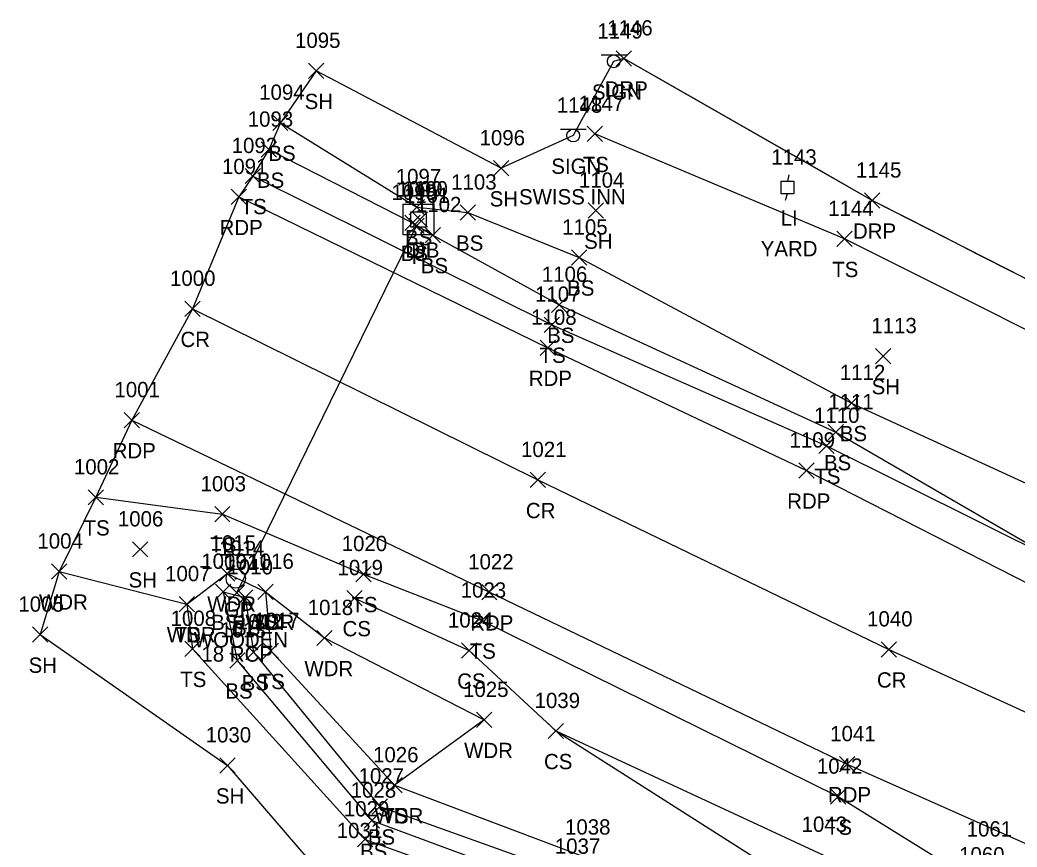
# Model space of a CAD drawing. Extents: x 1547013 to 1549434, y 267998 to 268739.
# Drawn here: x 1548262.7 to 1548393.1, y 268166.7 to 268275 of the extents above; entities that cross this region are included whole.
import ezdxf

# ---------------------------------------------------------------- set-up
doc = ezdxf.new("R2010")
doc.units = 0
for name, color, linetype in [('D_A', 7, 'Continuous'), ('D_C', 7, 'Continuous'), ('D_I', 7, 'Continuous'), ('D_TIC', 7, 'Continuous'), ('DCP', 7, 'Continuous'), ('DS', 7, 'Continuous'), ('L_A', 7, 'Continuous'), ('L_I', 7, 'Continuous'), ('L_TIC', 7, 'Continuous'), ('LAWA', 7, 'Continuous'), ('LELB', 7, 'Continuous'), ('LSOGP', 7, 'Continuous'), ('P_A', 7, 'Continuous'), ('P_I', 7, 'Continuous'), ('P_TIC', 7, 'Continuous'), ('PET', 7, 'Continuous'), ('PRC', 7, 'Continuous'), ('R_A', 7, 'Continuous'), ('R_C', 7, 'Continuous'), ('R_I', 7, 'Continuous'), ('R_TIC', 7, 'Continuous'), ('RDP', 7, 'Continuous'), ('RGP', 7, 'Continuous'), ('S_A', 7, 'Continuous'), ('S_C', 7, 'Continuous'), ('S_I', 7, 'Continuous'), ('SSGN', 7, 'Continuous'), ('U_A', 7, 'Continuous'), ('U_C', 7, 'Continuous'), ('U_I', 7, 'Continuous'), ('ULP', 7, 'Continuous')]:
    doc.layers.add(name, color=color, linetype=linetype)

msp = doc.modelspace()

# ---------------------------------------------------------------- linework, layer by layer
at = {"layer": 'D_TIC'}
for points in [[(1548313.99, 268247.85), (1548315.99, 268249.85)], [(1548315.99, 268247.85), (1548313.99, 268249.85)], [(1548313.54, 268247.01), (1548315.54, 268249.01)], [(1548315.54, 268247.01), (1548313.54, 268249.01)], [(1548290.04, 268198.97), (1548292.04, 268200.97)], [(1548292.04, 268198.97), (1548290.04, 268200.97)]]:
    msp.add_lwpolyline(points, dxfattribs=at)
at = {"layer": 'DCP'}
msp.add_lwpolyline([(1548291.04, 268199.97), (1548314.54, 268248.01)], dxfattribs=at)
at = {"layer": 'DS'}
for p, q in [((1548312.8, 268250.84), (1548316.8, 268250.84)), ((1548312.8, 268246.84), (1548312.8, 268250.84)), ((1548313.8, 268247.84), (1548313.8, 268249.84)), ((1548313.8, 268249.84), (1548315.8, 268249.84)), ((1548315.8, 268249.84), (1548315.8, 268247.84)), ((1548316.8, 268250.84), (1548316.8, 268246.84)), ((1548314.8, 268248.84), (1548314.8, 268248.84)), ((1548314.8, 268248.84), (1548314.8, 268248.84)), ((1548315.8, 268247.84), (1548313.8, 268247.84)), ((1548316.8, 268246.84), (1548312.8, 268246.84))]:
    msp.add_line(p, q, dxfattribs=at)
at = {"layer": 'L_TIC'}
for points in [[(1548300.42, 268267.29), (1548302.42, 268269.29)], [(1548302.42, 268267.29), (1548300.42, 268269.29)], [(1548295.73, 268260.5), (1548297.73, 268262.5)], [(1548297.73, 268260.5), (1548295.73, 268262.5)], [(1548336.89, 268259.04), (1548338.89, 268261.04)], [(1548338.89, 268259.04), (1548336.89, 268261.04)], [(1548294.23, 268256.98), (1548296.23, 268258.98)], [(1548296.23, 268256.98), (1548294.23, 268258.98)], [(1548324.63, 268254.54), (1548326.63, 268256.54)], [(1548326.63, 268254.54), (1548324.63, 268256.54)], [(1548292.13, 268253.53), (1548294.13, 268255.53)], [(1548294.13, 268253.53), (1548292.13, 268255.53)], [(1548313.6, 268249.46), (1548315.6, 268251.46)], [(1548315.6, 268249.46), (1548313.6, 268251.46)], [(1548337, 268249), (1548339, 268251)], [(1548339, 268249), (1548337, 268251)], [(1548320.28, 268248.75), (1548322.28, 268250.75)], [(1548322.28, 268248.75), (1548320.28, 268250.75)], [(1548313.04, 268247.41), (1548315.04, 268249.41)], [(1548315.04, 268247.41), (1548313.04, 268249.41)], [(1548315.67, 268245.8), (1548317.67, 268247.8)], [(1548317.67, 268245.8), (1548315.67, 268247.8)], [(1548369.54, 268245.3), (1548371.54, 268247.3)], [(1548371.54, 268245.3), (1548369.54, 268247.3)], [(1548334.82, 268242.87), (1548336.82, 268244.87)], [(1548336.82, 268242.87), (1548334.82, 268244.87)], [(1548332.21, 268236.68), (1548334.21, 268238.68)], [(1548334.21, 268236.68), (1548332.21, 268238.68)], [(1548331.25, 268234.07), (1548333.25, 268236.07)], [(1548333.25, 268234.07), (1548331.25, 268236.07)], [(1548374.62, 268229.96), (1548376.62, 268231.96)], [(1548376.62, 268229.96), (1548374.62, 268231.96)], [(1548370.49, 268223.82), (1548372.49, 268225.82)], [(1548372.49, 268223.82), (1548370.49, 268225.82)], [(1548368.42, 268220.01), (1548370.42, 268222.01)], [(1548370.42, 268220.01), (1548368.42, 268222.01)], [(1548367.2, 268218.22), (1548369.2, 268220.22)], [(1548369.2, 268218.22), (1548367.2, 268220.22)], [(1548271.57, 268211.48), (1548273.57, 268213.48)], [(1548273.57, 268211.48), (1548271.57, 268213.48)], [(1548288.14, 268209.26), (1548290.14, 268211.26)], [(1548290.14, 268209.26), (1548288.14, 268211.26)], [(1548277.38, 268204.67), (1548279.38, 268206.67)], [(1548279.38, 268204.67), (1548277.38, 268206.67)], [(1548266.79, 268201.77), (1548268.79, 268203.77)], [(1548268.79, 268201.77), (1548266.79, 268203.77)], [(1548288.79, 268201.51), (1548290.79, 268203.51)], [(1548290.79, 268201.51), (1548288.79, 268203.51)], [(1548306.62, 268201.44), (1548308.62, 268203.44)], [(1548308.62, 268201.44), (1548306.62, 268203.44)], [(1548288.24, 268199.12), (1548290.24, 268201.12)], [(1548290.24, 268199.12), (1548288.24, 268201.12)], [(1548288.24, 268199.12), (1548290.24, 268201.12)], [(1548290.24, 268199.12), (1548288.24, 268201.12)], [(1548291.11, 268198.39), (1548293.11, 268200.39)], [(1548293.11, 268198.39), (1548291.11, 268200.39)], [(1548293.8, 268199.12), (1548295.8, 268201.12)], [(1548295.8, 268199.12), (1548293.8, 268201.12)], [(1548293.8, 268199.12), (1548295.8, 268201.12)], [(1548295.8, 268199.12), (1548293.8, 268201.12)], [(1548305.43, 268198.29), (1548307.43, 268200.29)], [(1548307.43, 268198.29), (1548305.43, 268200.29)], [(1548283.5, 268197.5), (1548285.5, 268199.5)], [(1548285.5, 268197.5), (1548283.5, 268199.5)], [(1548283.5, 268197.5), (1548285.5, 268199.5)], [(1548285.5, 268197.5), (1548283.5, 268199.5)], [(1548322.1, 268195.35), (1548324.1, 268197.35)], [(1548324.1, 268195.35), (1548322.1, 268197.35)], [(1548264.3, 268193.51), (1548266.3, 268195.51)], [(1548266.3, 268193.51), (1548264.3, 268195.51)], [(1548301.52, 268193.07), (1548303.52, 268195.07)], [(1548303.52, 268193.07), (1548301.52, 268195.07)], [(1548284.22, 268191.65), (1548286.22, 268193.65)], [(1548286.22, 268191.65), (1548284.22, 268193.65)], [(1548292.23, 268191.21), (1548294.23, 268193.21)], [(1548294.23, 268191.21), (1548292.23, 268193.21)], [(1548294.49, 268191.38), (1548296.49, 268193.38)], [(1548296.49, 268191.38), (1548294.49, 268193.38)], [(1548320.43, 268191.43), (1548322.43, 268193.43)], [(1548322.43, 268191.43), (1548320.43, 268193.43)], [(1548290.1, 268190.14), (1548292.1, 268192.14)], [(1548292.1, 268190.14), (1548290.1, 268192.14)], [(1548322.41, 268182.35), (1548324.41, 268184.35)], [(1548324.41, 268182.35), (1548322.41, 268184.35)], [(1548331.78, 268180.9), (1548333.78, 268182.9)], [(1548333.78, 268180.9), (1548331.78, 268182.9)], [(1548331.78, 268180.9), (1548333.78, 268182.9)], [(1548333.78, 268180.9), (1548331.78, 268182.9)], [(1548288.82, 268176.4), (1548290.82, 268178.4)], [(1548290.82, 268176.4), (1548288.82, 268178.4)], [(1548310.68, 268173.8), (1548312.68, 268175.8)], [(1548312.68, 268173.8), (1548310.68, 268175.8)], [(1548310.68, 268173.8), (1548312.68, 268175.8)], [(1548312.68, 268173.8), (1548310.68, 268175.8)], [(1548368.71, 268172.31), (1548370.71, 268174.31)], [(1548370.71, 268172.31), (1548368.71, 268174.31)], [(1548308.74, 268171.03), (1548310.74, 268173.03)], [(1548310.74, 268171.03), (1548308.74, 268173.03)], [(1548307.71, 268169.17), (1548309.71, 268171.17)], [(1548309.71, 268169.17), (1548307.71, 268171.17)], [(1548306.82, 268166.72), (1548308.82, 268168.72)], [(1548308.82, 268166.72), (1548306.82, 268168.72)]]:
    msp.add_lwpolyline(points, dxfattribs=at)
at = {"layer": 'LAWA'}
msp.add_lwpolyline([(1548267.79, 268202.77), (1548284.5, 268198.5), (1548289.79, 268202.51), (1548294.8, 268200.12), (1548302.52, 268194.07), (1548323.41, 268183.35), (1548311.68, 268174.8)], dxfattribs=at)
at = {"layer": 'LELB'}
for points in [[(1548296.73, 268261.5), (1548314.6, 268250.46), (1548321.28, 268249.75), (1548335.82, 268243.87), (1548371.49, 268224.82), (1548401.22, 268211.16), (1548434.01, 268190.91)], [(1548293.13, 268254.53), (1548332.25, 268235.07), (1548368.2, 268219.22), (1548398.43, 268204.17), (1548432.39, 268188.56), (1548470.91, 268170.21), (1548496.62, 268162.55), (1548482.16, 268178.12), (1548462.07, 268192.9), (1548441.51, 268207.34), (1548411.84, 268225.63), (1548370.54, 268246.3), (1548337.89, 268260.04)], [(1548295.23, 268257.98), (1548314.04, 268248.41), (1548316.67, 268246.8), (1548333.21, 268237.68), (1548369.42, 268221.01), (1548398.43, 268204.17)], [(1548272.57, 268212.48), (1548289.14, 268210.26), (1548307.62, 268202.44), (1548323.1, 268196.35), (1548369.71, 268173.31), (1548388.46, 268161.7), (1548422.32, 268150.28), (1548459.33, 268134.33), (1548490.6, 268122.37), (1548528.34, 268109.13), (1548567.41, 268095.24), (1548592.2, 268086.56), (1548606.66, 268079.82), (1548620.32, 268072.15), (1548638.75, 268065.65), (1548644.4, 268061.61), (1548647.64, 268052.81), (1548649.6, 268041.05)], [(1548289.24, 268200.12), (1548292.11, 268199.39), (1548293.23, 268192.21), (1548309.74, 268172.03), (1548335.42, 268162.83), (1548365.1, 268153.15), (1548400.46, 268134.44), (1548414.42, 268125.58), (1548450.52, 268108.18), (1548480.18, 268096.43), (1548525.56, 268079.65), (1548533.49, 268078.22), (1548538.36, 268080.07), (1548548.83, 268079.87)], [(1548289.24, 268200.12), (1548291.1, 268191.14), (1548308.71, 268170.17), (1548334.15, 268160.77), (1548364.93, 268151.69), (1548400.57, 268132.64), (1548414.23, 268124.12), (1548450.61, 268106.02), (1548479.71, 268095.13), (1548525.1, 268077.98), (1548532.42, 268076.13)], [(1548294.8, 268200.12), (1548295.49, 268192.38), (1548311.68, 268174.8), (1548336.75, 268165.34), (1548365.8, 268156.23), (1548401.93, 268136.68), (1548414.05, 268129.03)], [(1548306.43, 268199.29), (1548321.43, 268192.43), (1548332.78, 268181.9), (1548367.71, 268165.7), (1548391.94, 268148.16), (1548415.52, 268137.54), (1548452.83, 268119.09), (1548479.13, 268107.94), (1548530.85, 268089.69)], [(1548284.5, 268198.5), (1548285.22, 268192.65), (1548307.82, 268167.72), (1548333.45, 268158.51), (1548364.16, 268149.82), (1548400.06, 268131.43), (1548413.58, 268123.14), (1548450.66, 268104.52)], [(1548332.78, 268181.9), (1548366.56, 268160.4), (1548391.94, 268148.16)]]:
    msp.add_lwpolyline(points, dxfattribs=at)
at = {"layer": 'LSOGP'}
msp.add_lwpolyline([(1548397.39, 268239.51), (1548392.75, 268241.87), (1548388.1, 268244.23), (1548383.46, 268246.6), (1548378.82, 268248.96), (1548374.18, 268251.32), (1548366.05, 268255.97), (1548357.93, 268260.62), (1548349.8, 268265.27), (1548341.68, 268269.92), (1548340.34, 268269.52), (1548335.03, 268259.81), (1548325.63, 268255.54), (1548301.42, 268268.29), (1548296.73, 268261.5), (1548295.23, 268257.98), (1548293.13, 268254.53), (1548291.29, 268251.79), (1548285.23, 268237.15), (1548277.31, 268222.58), (1548272.57, 268212.48), (1548267.79, 268202.77), (1548265.3, 268194.51), (1548289.82, 268177.4), (1548304.9, 268159.85)], dxfattribs=at)
at = {"layer": 'P_TIC'}
for points in [[(1548290.29, 268250.79), (1548292.29, 268252.79)], [(1548292.29, 268250.79), (1548290.29, 268252.79)], [(1548284.23, 268236.15), (1548286.23, 268238.15)], [(1548286.23, 268236.15), (1548284.23, 268238.15)], [(1548330.75, 268231.06), (1548332.75, 268233.06)], [(1548332.75, 268231.06), (1548330.75, 268233.06)], [(1548276.31, 268221.58), (1548278.31, 268223.58)], [(1548278.31, 268221.58), (1548276.31, 268223.58)], [(1548329.43, 268213.75), (1548331.43, 268215.75)], [(1548331.43, 268213.75), (1548329.43, 268215.75)], [(1548364.57, 268214.99), (1548366.57, 268216.99)], [(1548366.57, 268214.99), (1548364.57, 268216.99)], [(1548323.08, 268199.05), (1548325.08, 268201.05)], [(1548325.08, 268199.05), (1548323.08, 268201.05)], [(1548375.37, 268191.58), (1548377.37, 268193.58)], [(1548377.37, 268191.58), (1548375.37, 268193.58)], [(1548369.89, 268176.56), (1548371.89, 268178.56)], [(1548371.89, 268176.56), (1548369.89, 268178.56)]]:
    msp.add_lwpolyline(points, dxfattribs=at)
at = {"layer": 'PET'}
for points in [[(1548291.29, 268251.79), (1548331.75, 268232.06), (1548365.57, 268215.99), (1548397.04, 268199.92), (1548430.53, 268185.01), (1548469.56, 268167.88), (1548505.57, 268153.53), (1548548.45, 268139.73), (1548572.84, 268130.65), (1548596.65, 268123.57), (1548616.57, 268118.19), (1548655.34, 268109.04), (1548680.93, 268103.12), (1548700.8, 268099.76), (1548753.55, 268092.31), (1548788.11, 268088.53), (1548842.08, 268084.26), (1548868.98, 268083.24)], [(1548277.31, 268222.58), (1548324.08, 268200.05), (1548370.89, 268177.56), (1548421.34, 268155.12), (1548457.66, 268139.55), (1548491.25, 268126.1), (1548528.96, 268112.02), (1548568.2, 268099.41), (1548604.28, 268089.49), (1548621.9, 268083.87), (1548638.12, 268079.83), (1548660.94, 268075.04), (1548683.04, 268070.81), (1548718.59, 268065.27), (1548750.02, 268060.75), (1548786.09, 268057.26), (1548818, 268054.36), (1548866.14, 268051.84)]]:
    msp.add_lwpolyline(points, dxfattribs=at)
at = {"layer": 'PRC'}
msp.add_lwpolyline([(1548285.23, 268237.15), (1548330.43, 268214.75), (1548376.37, 268192.58), (1548426.54, 268169.59), (1548464.29, 268153.5), (1548497.35, 268140.09), (1548534.69, 268126.49), (1548572.93, 268114.69), (1548608.02, 268104.77), (1548637.81, 268097.38), (1548663.07, 268091.69), (1548686.38, 268086.96), (1548723.69, 268081.05), (1548751.9, 268076.9), (1548786.74, 268073.36), (1548818.76, 268070.54), (1548866.8, 268068.08)], dxfattribs=at)
at = {"layer": 'R_TIC'}
for points in [[(1548340.68, 268268.92), (1548342.68, 268270.92)], [(1548342.68, 268268.92), (1548340.68, 268270.92)], [(1548373.18, 268250.32), (1548375.18, 268252.32)], [(1548375.18, 268250.32), (1548373.18, 268252.32)]]:
    msp.add_lwpolyline(points, dxfattribs=at)
at = {"layer": 'RDP'}
msp.add_lwpolyline([(1548505.57, 268153.53), (1548507.08, 268156.6), (1548497.9, 268167.16), (1548485.25, 268181.3), (1548463.54, 268201.58), (1548445.25, 268213.44), (1548411.31, 268232.42), (1548374.18, 268251.32), (1548341.68, 268269.92)], dxfattribs=at)
at = {"layer": 'RGP'}
msp.add_line((1548290.9, 268201.84), (1548290.9, 268201.84), dxfattribs=at)
for radius in [1.25, 0.0833]:
    msp.add_circle((1548290.9, 268201.84), radius, dxfattribs=at)
at = {"layer": 'SSGN'}
for p, q in [((1548338.71, 268270.37), (1548342.05, 268270.37)), ((1548340.36, 268269.54), (1548340.36, 268269.54)), ((1548333.41, 268260.67), (1548336.74, 268260.67)), ((1548335.05, 268259.83), (1548335.05, 268259.83))]:
    msp.add_line(p, q, dxfattribs=at)
for centre in [(1548340.36, 268269.54), (1548335.05, 268259.83)]:
    msp.add_circle(centre, 0.833, dxfattribs=at)
at = {"layer": 'ULP'}
for p, q in [((1548362.26, 268252.19), (1548362.26, 268253.85)), ((1548362.26, 268253.85), (1548363.93, 268253.85)), ((1548363.26, 268254.69), (1548363.09, 268253.85)), ((1548363.93, 268253.85), (1548363.93, 268252.19)), ((1548363.09, 268253.02), (1548363.09, 268253.02)), ((1548363.93, 268252.19), (1548362.26, 268252.19)), ((1548362.84, 268251.35), (1548363.09, 268252.19))]:
    msp.add_line(p, q, dxfattribs=at)

# ---------------------------------------------------------------- texts
at = {"layer": 'D_A'}
for s, p in [('DIB', (1548313.09, 268243.85)), ('DI', (1548313.86, 268243.84)), ('P', (1548313.91, 268243.01)), ('P', (1548290.42, 268194.97))]:
    msp.add_text(s, height=2, dxfattribs=at).set_placement(p)
at = {"layer": 'D_C'}
msp.add_text('18 RCP', height=2, dxfattribs=at).set_placement((1548286.4, 268190.97))
at = {"layer": 'D_I'}
for s, p in [('1099', (1548312.02, 268251.84)), ('1100', (1548312.7, 268251.85)), ('1101', (1548312.9, 268251.01)), ('1011', (1548289.4, 268202.97))]:
    msp.add_text(s, height=2, dxfattribs=at).set_placement(p)
at = {"layer": 'L_A'}
for s, p in [('SH', (1548299.91, 268263.29)), ('BS', (1548295.17, 268256.5)), ('TS', (1548336.3, 268255.04)), ('BS', (1548293.67, 268252.98)), ('SH', (1548324.12, 268250.54)), ('TS', (1548291.54, 268249.53)), ('BS', (1548313.04, 268245.46)), ('BS', (1548319.72, 268244.75)), ('SH', (1548336.49, 268245)), ('BS', (1548312.48, 268243.41)), ('BS', (1548315.11, 268241.8)), ('TS', (1548368.95, 268241.3)), ('BS', (1548334.26, 268238.87)), ('BS', (1548331.65, 268232.68)), ('TS', (1548330.66, 268230.07)), ('SH', (1548374.1, 268225.96)), ('BS', (1548369.94, 268219.82)), ('BS', (1548367.86, 268216.01)), ('TS', (1548366.61, 268214.22)), ('TS', (1548270.98, 268207.48)), ('TS', (1548287.55, 268205.26)), ('SH', (1548276.87, 268200.67)), ('WDR', (1548265.15, 268197.77)), ('WDR', (1548287.16, 268197.51)), ('TS', (1548306.03, 268197.44)), ('BS', (1548287.68, 268195.12)), ('BS', (1548287.68, 268195.12)), ('BS', (1548290.55, 268194.39)), ('WDR', (1548292.16, 268195.12)), ('TS', (1548293.21, 268195.12)), ('CS', (1548304.87, 268194.29)), ('WDR', (1548281.87, 268193.5)), ('TS', (1548282.91, 268193.5)), ('TS', (1548321.51, 268191.35)), ('SH', (1548263.79, 268189.51)), ('WDR', (1548299.88, 268189.07)), ('TS', (1548283.63, 268187.65)), ('BS', (1548291.67, 268187.21)), ('TS', (1548293.9, 268187.38)), ('CS', (1548319.87, 268187.43)), ('BS', (1548289.54, 268186.14)), ('WDR', (1548320.78, 268178.35)), ('CS', (1548331.23, 268176.9)), ('CS', (1548331.23, 268176.9)), ('SH', (1548288.3, 268172.4)), ('WDR', (1548309.05, 268169.8)), ('TS', (1548310.09, 268169.8)), ('TS', (1548368.12, 268168.31)), ('BS', (1548308.18, 268167.03)), ('BS', (1548307.15, 268165.17))]:
    msp.add_text(s, height=2, dxfattribs=at).set_placement(p)
at = {"layer": 'L_I'}
for s, p in [('1095', (1548298.65, 268271.29)), ('1094', (1548293.96, 268264.5)), ('1147', (1548335.77, 268263.04)), ('1093', (1548292.46, 268260.98)), ('1096', (1548322.8, 268258.54)), ('1092', (1548290.36, 268257.53)), ('1097', (1548311.83, 268253.46)), ('1104', (1548335.8, 268253)), ('1103', (1548319.08, 268252.75)), ('1098', (1548311.26, 268251.41)), ('1102', (1548314.47, 268249.8)), ('1144', (1548368.42, 268249.3)), ('1105', (1548333.61, 268246.87)), ('1106', (1548330.95, 268240.68)), ('1107', (1548330.05, 268238.07)), ('1113', (1548374.06, 268233.96)), ('1112', (1548369.94, 268227.82)), ('1111', (1548368.43, 268224.01)), ('1110', (1548366.56, 268222.22)), ('1002', (1548269.72, 268215.48)), ('1003', (1548286.29, 268213.26)), ('1006', (1548275.47, 268208.67)), ('1004', (1548264.94, 268205.77)), ('1015', (1548287.59, 268205.51)), ('1020', (1548304.76, 268205.44)), ('1009', (1548286.38, 268203.12)), ('1009', (1548286.38, 268203.12)), ('1010', (1548289.81, 268202.39)), ('1016', (1548292.54, 268203.12)), ('1016', (1548292.54, 268203.12)), ('1019', (1548304.21, 268202.29)), ('1007', (1548281.65, 268201.5)), ('1007', (1548281.65, 268201.5)), ('1023', (1548320.33, 268199.35)), ('1005', (1548262.45, 268197.51)), ('1018', (1548300.31, 268197.07)), ('1008', (1548282.37, 268195.65)), ('1024', (1548318.66, 268195.43)), ('1013', (1548288.89, 268194.14)), ('1012', (1548291.03, 268195.21)), ('1017', (1548293.29, 268195.38)), ('1025', (1548320.64, 268186.35)), ('1039', (1548330, 268184.9)), ('1039', (1548330, 268184.9)), ('1030', (1548286.96, 268180.4)), ('1026', (1548308.86, 268177.8)), ('1026', (1548308.86, 268177.8)), ('1042', (1548366.94, 268176.31)), ('1027', (1548306.97, 268175.03)), ('1028', (1548305.94, 268173.17)), ('1029', (1548305.04, 268170.72)), ('1038', (1548333.98, 268168.34)), ('1043', (1548364.94, 268168.7)), ('1031', (1548304.11, 268167.88)), ('1037', (1548332.65, 268165.83)), ('1060', (1548385.55, 268164.7))]:
    msp.add_text(s, height=2, dxfattribs=at).set_placement(p)
at = {"layer": 'P_A'}
for s, p in [('RDP', (1548288.78, 268246.79)), ('CR', (1548283.66, 268232.15)), ('RDP', (1548329.24, 268227.06)), ('RDP', (1548274.79, 268217.58)), ('RDP', (1548363.06, 268210.99)), ('CR', (1548328.86, 268209.75)), ('RDP', (1548321.57, 268195.05)), ('CR', (1548374.8, 268187.58)), ('RDP', (1548368.38, 268172.56))]:
    msp.add_text(s, height=2, dxfattribs=at).set_placement(p)
at = {"layer": 'P_I'}
for s, p in [('1091', (1548289.09, 268254.79)), ('1000', (1548282.29, 268240.15)), ('1108', (1548329.55, 268235.06)), ('1001', (1548275.02, 268225.58)), ('1109', (1548363.36, 268218.99)), ('1021', (1548328.23, 268217.75)), ('1022', (1548321.31, 268203.05)), ('1040', (1548373.51, 268195.58)), ('1041', (1548368.68, 268180.56))]:
    msp.add_text(s, height=2, dxfattribs=at).set_placement(p)
at = {"layer": 'R_A'}
for s, p in [('DRP', (1548339.17, 268264.92)), ('DRP', (1548371.66, 268246.32)), ('GP', (1548289.33, 268196.84))]:
    msp.add_text(s, height=2, dxfattribs=at).set_placement(p)
at = {"layer": 'R_C'}
msp.add_text('WOODEN', height=2, dxfattribs=at).set_placement((1548285.41, 268192.84))
at = {"layer": 'R_I'}
for s, p in [('1146', (1548339.5, 268272.92)), ('1145', (1548372.05, 268254.32)), ('1014', (1548288.69, 268204.84)), ('1061', (1548386.54, 268168.09))]:
    msp.add_text(s, height=2, dxfattribs=at).set_placement(p)
at = {"layer": 'S_A'}
for p in [(1548337.5, 268264.52), (1548332.19, 268254.81)]:
    msp.add_text('SIGN', height=2, dxfattribs=at).set_placement(p)
at = {"layer": 'S_C'}
msp.add_text('SWISS INN', height=2, dxfattribs=at).set_placement((1548327.96, 268250.81))
at = {"layer": 'S_I'}
for s, p in [('1149', (1548338.21, 268272.52)), ('1148', (1548332.91, 268262.81))]:
    msp.add_text(s, height=2, dxfattribs=at).set_placement(p)
at = {"layer": 'U_A'}
msp.add_text('LI', height=2, dxfattribs=at).set_placement((1548362.2, 268248.02))
at = {"layer": 'U_C'}
msp.add_text('YARD', height=2, dxfattribs=at).set_placement((1548359.59, 268244.02))
at = {"layer": 'U_I'}
msp.add_text('1143', height=2, dxfattribs=at).set_placement((1548360.97, 268256.02))

doc.saveas('drawing.dxf')
